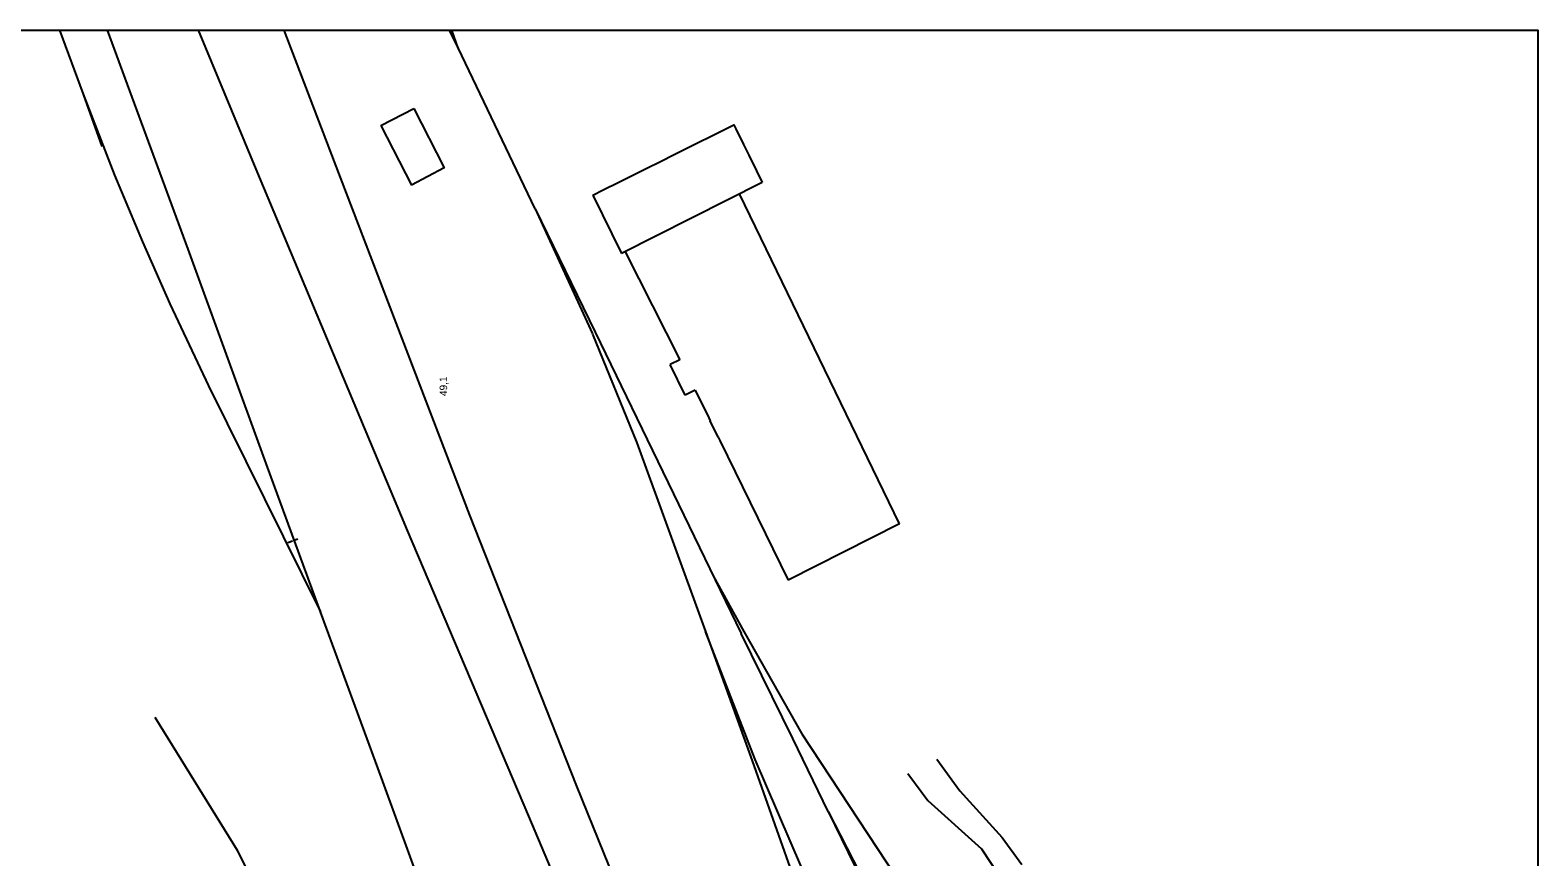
# Model space of a CAD drawing. Extents: x -932963 to -932666, y -737039 to -736000.
# Drawn here: x -932796.60368 to -932796.58871, y -736668.94879 to -736668.94058 of the extents above; entities that cross this region are included whole.
import ezdxf

# ---------------------------------------------------------------- set-up
doc = ezdxf.new("R2010")
doc.units = 0
for name, color, linetype in [('Border', 7, 'Continuous'), ('Implicitní', 7, 'Continuous'), ('Koleje_stávající', 7, 'Continuous'), ('Komunikace_stávající', 7, 'Continuous'), ('Objekty_stávající', 7, 'Continuous'), ('SL_05_KOMUNIKACE', 7, 'Continuous')]:
    doc.layers.add(name, color=color, linetype=linetype)

# ---------------------------------------------------------------- blocks, each defined once
blk = doc.blocks.new('5.121_1')
at = {"layer": 'Implicitní'}
blk.add_line((0, 0), (0, 0.0005), dxfattribs=at)
blk = doc.blocks.new('přehledka')
at = {"layer": 'Border'}
blk.add_lwpolyline([(0, 0), (0.099915, 0), (0.099915, -0.065218), (0, -0.065218)], close=True, dxfattribs=at)
at = {"layer": 'Koleje_stávající'}
for p, q in [((0.098646, -0.03634), (0.097605, -0.036709)), ((0.099551, -0.043788), (0.099915, -0.043611)), ((0.096368, -0.045312), (0.099561, -0.043783))]:
    blk.add_line(p, q, dxfattribs=at)
for points in [[(0.099915, -0.035871), (0.098646, -0.03634), (0.097038, -0.03696), (0.09571, -0.037516), (0.09448, -0.03806), (0.092852, -0.038824), (0.088366, -0.04105)], [(0.070214, -0.047688), (0.073116, -0.046624), (0.075926, -0.045598), (0.079086, -0.044442), (0.082654, -0.043138), (0.085068, -0.04226), (0.088366, -0.04105), (0.091314, -0.039974), (0.09557, -0.038422), (0.09846, -0.037358), (0.099915, -0.036822)], [(0.034457, -0.065218), (0.036094, -0.06463), (0.042022, -0.062434), (0.046232, -0.060838), (0.053854, -0.05786), (0.057568, -0.05638), (0.066464, -0.052712), (0.072204, -0.050292), (0.078868, -0.04748), (0.08431, -0.045184), (0.089984, -0.04278), (0.097074, -0.039804), (0.099915, -0.038627)], [(0.03708, -0.065218), (0.04231, -0.06328), (0.04657, -0.061666), (0.054136, -0.05872), (0.066806, -0.053566), (0.072606, -0.051164), (0.079336, -0.048394), (0.084902, -0.046136), (0.090286, -0.044012), (0.0973, -0.041326), (0.099915, -0.040329)], [(0.09956, -0.043784), (0.099915, -0.043657)], [(0.096369, -0.045311), (0.09392, -0.046503), (0.087936, -0.049405)], [(0.096368, -0.045311), (0.093888, -0.046448)], [(0.093882, -0.046451), (0.091721, -0.04733), (0.087973, -0.048691)], [(0.087976, -0.04869), (0.085436, -0.049675), (0.0833, -0.050595), (0.07568, -0.054149), (0.069227, -0.057414)], [(0.087973, -0.048691), (0.08541, -0.049617), (0.081712, -0.050929)], [(0.089083, -0.048849), (0.087974, -0.049455), (0.085947, -0.050608), (0.079133, -0.055094)], [(0.084401, -0.051131), (0.085851, -0.050427), (0.087937, -0.049405)], [(0.084401, -0.051131), (0.081958, -0.052321), (0.078416, -0.054033), (0.075967, -0.055229), (0.070542, -0.057871), (0.065749, -0.060528), (0.059036, -0.065218)], [(0.084401, -0.051131), (0.08199, -0.052367), (0.07512, -0.056635), (0.0672, -0.061933)]]:
    blk.add_lwpolyline(points, dxfattribs=at)
at = {"layer": 'Komunikace_stávající'}
for points in [[(0.086278, -0.037758), (0.083634, -0.039394), (0.082248, -0.040084), (0.081559, -0.040377), (0.07832, -0.04125), (0.0753, -0.042404), (0.07175, -0.043768), (0.067214, -0.04551), (0.06388, -0.04677), (0.063028, -0.047065), (0.06121, -0.047734), (0.056748, -0.049352), (0.052088, -0.051014), (0.049772, -0.051898), (0.048486, -0.05233), (0.047346, -0.0527), (0.043028, -0.054132), (0.038862, -0.05539), (0.036736, -0.05607), (0.036645, -0.056105)], [(0.085156, -0.05271), (0.08462, -0.053106), (0.08366, -0.054176), (0.080928, -0.055976)], [(0.085442, -0.053284), (0.08481, -0.053742), (0.083884, -0.054582), (0.083348, -0.054974)]]:
    blk.add_lwpolyline(points, dxfattribs=at)
at = {"layer": 'Objekty_stávající'}
for p, q in [((0.098023, -0.042251), (0.09684, -0.042858)), ((0.098023, -0.042251), (0.098358, -0.042904)), ((0.095514, -0.047099), (0.093372, -0.048183)), ((0.093372, -0.048183), (0.093278, -0.04799)), ((0.092768, -0.048489), (0.09267, -0.048288)), ((0.090116, -0.052546), (0.096662, -0.049367))]:
    blk.add_line(p, q, dxfattribs=at)
for points in [[(0.098358, -0.042904), (0.097184, -0.043506), (0.09684, -0.042858)], [(0.09664, -0.04646), (0.095478, -0.047028)], [(0.09664, -0.04646), (0.096742, -0.046665), (0.096896, -0.046974), (0.097026, -0.047235), (0.09718, -0.047545), (0.0973, -0.047785), (0.09745, -0.048087), (0.098034, -0.049258), (0.097953, -0.049298), (0.097644, -0.049451), (0.097431, -0.049556), (0.097124, -0.049707), (0.096892, -0.049822)], [(0.096892, -0.049822), (0.095478, -0.047028)], [(0.09267, -0.048288), (0.093278, -0.04799)], [(0.092768, -0.048489), (0.09222, -0.048757), (0.092157, -0.048788)], [(0.091835, -0.048945), (0.092157, -0.048788)], [(0.091835, -0.048945), (0.091767, -0.048978), (0.088998, -0.050334)], [(0.090116, -0.052546), (0.088998, -0.050334)]]:
    blk.add_lwpolyline(points, dxfattribs=at)
at = {"layer": 'Koleje_stávající', "xscale": 0.2, "yscale": 0.20000000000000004, "rotation": 19.393445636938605}
for p in [(0.08977, -0.040493), (0.089808, -0.040599)]:
    blk.add_blockref('5.121_1', p, dxfattribs=at)
at = {"layer": 'Koleje_stávající'}
blk.add_text('49,1', height=0.00015, dxfattribs=at).set_placement((0.09265, -0.043564))

msp = doc.modelspace()

# ---------------------------------------------------------------- block references
at = {"layer": 'SL_05_KOMUNIKACE', "xscale": 0.5, "yscale": 0.5, "rotation": 90}
msp.add_blockref('přehledka', (-932796.621319, -736668.99054), dxfattribs=at)

doc.saveas('drawing.dxf')
